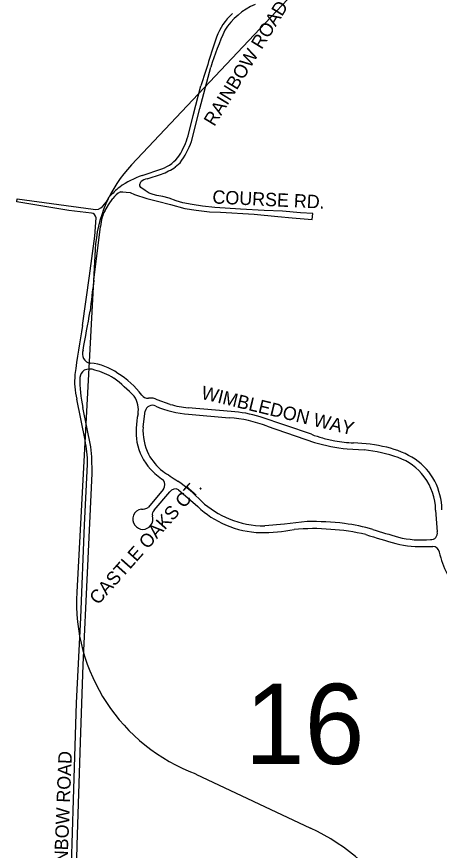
# Model space of a CAD drawing. Extents: x 0 to 712119, y 0 to 761125.
# Drawn here: x 660196 to 661775, y 720502 to 723620 of the extents above; entities that cross this region are included whole.
import ezdxf

# ---------------------------------------------------------------- set-up
doc = ezdxf.new("R2010")
doc.units = 0
for name, color, linetype in [('PAVED ROADS', 7, 'Continuous'), ('Priority 16', 7, 'Continuous'), ('street names', 7, 'Continuous')]:
    doc.layers.add(name, color=color, linetype=linetype)

msp = doc.modelspace()

# ---------------------------------------------------------------- linework, layer by layer
at = {"layer": 'PAVED ROADS'}
for points in [[(660848.5, 723153.3), (660880, 723276.5), (660920.5, 723431)], [(660836, 723174), (660855.3, 723250), (660884, 723361.5)], [(660788.4, 723058.1), (660806.3, 723073.9)], [(660664.5, 723026.5), (660738, 723050.5)], [(660683.5, 723013), (660736.5, 723031)], [(660583, 722965), (660592.5, 722964.5), (660604.5, 722964), (660620, 722962.5), (660635.5, 722955.5), (660682, 722939.5), (660722, 722930), (660770, 722917.5), (660824.5, 722902), (660866.5, 722896.5), (660915.5, 722890.5), (660957.5, 722889), (661082.5, 722882), (661171.5, 722873), (661225.5, 722868), (661300, 722862), (661302, 722883.5), (661256.5, 722886.5), (661188.5, 722892), (661121, 722894.5), (661032.5, 722899.5), (660936.5, 722906), (660890, 722911), (660851, 722917), (660817, 722924), (660792, 722931), (660765, 722941), (660741.5, 722947), (660719, 722951.5), (660705.5, 722955.5), (660691, 722960.5), (660676, 722970), (660660, 722981), (660655.5, 722987), (660656, 722992.5), (660656.5, 722996), (660657.9, 722998.6), (660659.5, 723002)], [(660475, 722885.5), (660390, 722895.5), (660195.5, 722927.5), (660197.5, 722939), (660481.5, 722900)], [(660518, 722910.9), (660530, 722926.5), (660541.5, 722946)], [(660524.4, 722892.7), (660538.3, 722916.3), (660554.3, 722939.6)], [(660441.5, 722464.5), (660468, 722650.5), (660487, 722799.5), (660492, 722868)], [(660484, 722634), (660509, 722835.5)], [(660451, 722036.5), (660420, 722190)], [(660769, 722170), (660721, 722187.5)], [(660473, 722011.5), (660443, 722158.5)], [(660997, 722143), (660836.5, 722157)], [(660668, 722085), (660672, 722115.5), (660676, 722144.5)], [(660838, 722133), (660989.5, 722120)], [(661297.5, 722058), (661105, 722123)], [(661131.5, 722088.5), (661309, 722028)], [(661430.5, 722003.5), (661494, 721999.5)], [(660390.6, 720154.9), (660390.6, 720154.9), (660390.6, 720154.9), (660392.6, 720201.8), (660408.1, 720691.1), (660418.5, 721053.5), (660435.5, 721371.5), (660449, 721718), (660460.5, 721947)], [(660412.4, 720158.9), (660421.8, 720522), (660434.5, 720906.5), (660443.5, 721196), (660460.5, 721540), (660477.5, 721911.5)], [(660744.5, 721853), (660687.5, 721784.5)], [(660709, 721774.5), (660768, 721843)], [(660800.5, 721850.5), (660872, 721788)], [(661761, 721774.5), (661767, 721693.5)], [(661281.5, 721731.5), (661196.5, 721722.5), (661122.5, 721716)], [(661728.5, 721639), (661750.5, 721639)]]:
    msp.add_lwpolyline(points, dxfattribs=at)
for centre, radius, start, end in [((661191.7, 723428), 260.4, 113.8809, 147.0942), ((661141.5, 723473.7), 210.9, 131.5314, 160.6645), ((662409.2, 722945.9), 1565.7, 156.5291, 161.9513), ((679013, 717634.7), 19012.1, 161.89305, 162.46917), ((660501.5, 723278.3), 350.4, 329.691, 342.6777), ((660581.8, 723244.1), 281.7, 322.8306, 341.1923), ((660688.6, 723182.6), 141, 290.4955, 324.8929), ((660655.4, 723249.5), 233.1, 290.3639, 304.809), ((660780.8, 722702.3), 344.4, 109.7341, 125.5579), ((660685.3, 722977.4), 35.7, 92.9001, 136.3471), ((660807.2, 722701.2), 361.3, 128.8646, 137.3424), ((660638.8, 722873), 107.6, 121.2633, 141.7566), ((660490.2, 722937.4), 38.5, 256.8699, 316.3199), ((660471.6, 722865.2), 20.6, 7.8573, 80.482), ((660678.9, 722823.7), 170.3, 164.0718, 176.0388), ((660633.2, 722834.3), 123.5, 151.7791, 162.9755), ((663522, 722208.5), 3067.7, 172.0271, 174.2095), ((641514.7, 725895.2), 19253.8, 349.45778, 349.89788), ((664151.8, 721798.3), 3769.7, 169.8212, 172.6407), ((660487.3, 722359.1), 45.8, 162.9797, 202.5608), ((660476, 722359.6), 35.9, 210.3353, 262.785), ((660456.5, 722127.9), 196.7, 53.503, 85.6313), ((660661.3, 722253.8), 249.6, 173.6957, 194.8066), ((660468.7, 722267.3), 36.9, 125.0773, 174.2755), ((660468.7, 722250.6), 51.5, 68.5502, 114.314), ((660422.8, 722048.7), 258, 58.4104, 75.487), ((660394, 721997.7), 339.6, 37.6172, 58.0908), ((660852.5, 722255.3), 420.8, 177.8654, 193.3036), ((660122.7, 721698), 717.7, 44.4475, 52.656), ((660555.4, 722149), 94.8, 350.8898, 32.8875), ((660685.2, 722219.3), 26.4, 212.7149, 276.0031), ((660695.8, 722137.8), 55.7, 63.0602, 98.0151), ((660702.6, 722139.5), 27, 62.5876, 169.3612), ((660872.3, 722534.5), 402.9, 247.0254, 265.1214), ((660880.8, 722568.5), 413.9, 254.3353, 263.8621), ((660932.2, 722069.1), 290.6, 167.0885, 188.0267), ((660956.4, 721634.8), 486.3, 68.8922, 86.093), ((660979.9, 721749.1), 394.2, 71.5008, 87.5163), ((660862.7, 722071.5), 195.2, 176.0239, 206.8676), ((661444.1, 722438.1), 407.4, 248.91, 255.0505), ((660022.3, 721945.7), 438.2, 0.1645, 11.9535), ((660850.1, 722069.7), 209.7, 191.3182, 222.494), ((661500.2, 722662.7), 662.9, 253.235, 263.9638), ((661474.8, 722506.8), 481.8, 253.6246, 259.1935), ((661470.3, 722504), 478.3, 259.6637, 268.1053), ((661427.8, 721351.3), 675.2, 77.1056, 87.7354), ((659469.1, 721916.2), 1008.4, 359.7316, 5.4215), ((661447, 721492.8), 508.9, 70.0041, 84.6996), ((661497.8, 721666.7), 352.2, 57.8905, 76.7552), ((660867.6, 722078.8), 202.9, 208.0784, 231.4627), ((661553, 721776.8), 205.8, 36.4311, 70.7017), ((661553.1, 721774.9), 231.4, 0.2771, 55.2524), ((660870.4, 722085.1), 235.1, 221.9185, 237.1776), ((679277.4, 749881.8), 33547.7, 236.45903, 236.57535), ((660720.7, 721869.2), 28.8, 325.6197, 39.3595), ((660483.1, 721423.9), 556.3, 43.5949, 55.525), ((661548.6, 721771.5), 212.5, 0.7962, 36.86), ((660788.1, 721830), 24, 58.8722, 147.1171), ((661137, 722088), 376.4, 228.1822, 247.0181), ((660666.8, 721741.6), 37.3, 98.1706, 218.2265), ((660665, 721822.6), 44.2, 265.4296, 300.5596), ((661109.5, 722034.1), 342, 226.0145, 247.1129), ((660667.6, 721741), 36.9, 321.487, 19.0578), ((660727, 721757.3), 24.9, 136.3229, 190.0342), ((660667.2, 721737.9), 35.5, 213.2195, 325.8094), ((661114.4, 722037.4), 347, 246.5839, 268.7772), ((661118.4, 722051.6), 335.6, 247.5098, 270.7031), ((661304.6, 720798.9), 932.9, 82.8341, 91.4206), ((661338.3, 721078.3), 651.4, 73.2115, 82.7103), ((661112.9, 722311.6), 621.1, 269.457, 281.0558), ((661303.2, 720973.9), 731.5, 84.836, 95.5822), ((661322.3, 720934.2), 769.7, 76.611, 86.5193), ((662652.8, 725347), 3840.9, 252.5421, 254.2932), ((663847.2, 729304.2), 7948.5, 253.02415, 253.74256), ((661743.7, 721688.3), 23.9, 265.9688, 12.5039), ((661708.8, 722026.6), 363.7, 256.1873, 275.2344), ((661703.8, 722007.6), 369.4, 255.7745, 273.8366), ((661750.4, 721614.1), 24.9, 7.7839, 89.6789), ((662064.5, 721676.6), 295.4, 191.5352, 208.376)]:
    msp.add_arc(centre, radius, start, end, dxfattribs=at)
at = {"layer": 'Priority 16'}
for points in [[(661729.7, 724239.1), (660624.2, 723065.4)], [(660488.9, 722749.5), (660419.8, 721468.1)], [(660865.5, 720787.6), (661294, 720585.1)]]:
    msp.add_lwpolyline(points, dxfattribs=at)
for centre, radius, start, end in [((660988.2, 722722.6), 500, 136.7131, 176.9129), ((661105.7, 721431.2), 686.9, 176.9129, 249.533), ((660956.4, 719866.5), 794, 32.085, 64.8332)]:
    msp.add_arc(centre, radius, start, end, dxfattribs=at)

# ---------------------------------------------------------------- texts
msp.add_text('16', height=300, dxfattribs=at).set_placement((661048.6, 720825.1))
at = {"layer": 'street names'}
for s, rotation, p in [('RAINBOW ROAD', 58.4407, (660934, 723206.8)), ('COURSE RD.', 357.3295, (660926.1, 722921.4)), ('WIMBLEDON WAY', 346.39, (660882, 722191.6)), ('CASTLE OAKS CT.', 48.4151, (660499.7, 721417.6)), ('RAINBOW ROAD', 87.7183, (660380.9, 720341.8))]:
    msp.add_text(s, height=50, rotation=rotation, dxfattribs=at).set_placement(p)

doc.saveas('drawing.dxf')
